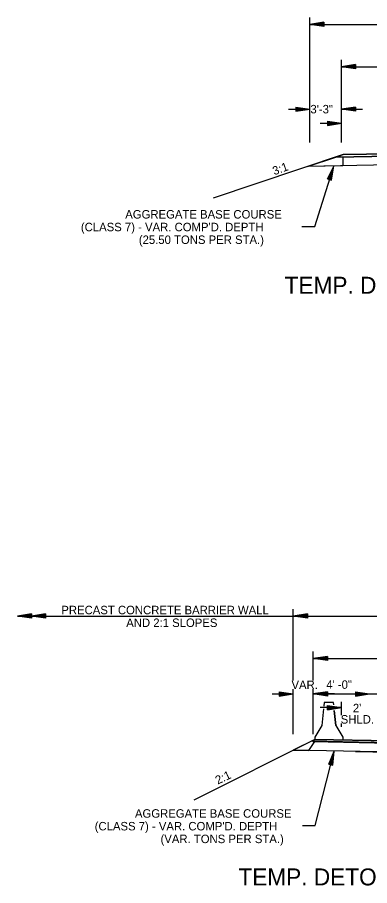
# Model space of a CAD drawing. Extents: x 138 to 3619, y -519 to 1449.
# Drawn here: x 2153 to 2402, y 302 to 917 of the extents above; entities that cross this region are included whole.
import ezdxf

# ---------------------------------------------------------------- set-up
doc = ezdxf.new("R2010")
doc.units = 0
for name, color, linetype in [('R_Annotation', 7, 'Continuous'), ('R_Barrier Wall', 7, 'Continuous'), ('R_Dimension', 7, 'Continuous'), ('R_No Plot', 7, 'Continuous')]:
    doc.layers.add(name, color=color, linetype=linetype)

msp = doc.modelspace()

# ---------------------------------------------------------------- linework, layer by layer
at = {"layer": 'R_Annotation'}
for p, q in [((2383.54, 820.01), (2291.37, 789.28)), ((2502.36, 820.55), (2378.33, 818.27)), ((2502.36, 822.22), (2383.54, 820.01)), ((2502.36, 814.3), (2358.31, 811.6)), ((2363.43, 405.81), (2277.65, 362.92)), ((2363.43, 405.81), (2362.09, 404.48)), ((2363.43, 405.81), (2642.36, 400.61)), ((2502.36, 401.55), (2360.91, 404.56)), ((2392.36, 397.37), (2658.85, 392.36))]:
    msp.add_line(p, q, dxfattribs=at)
msp.add_lwpolyline([(2502.36, 395.3), (2348.2, 398.2)], dxfattribs=at)
at = {"layer": 'R_Barrier Wall'}
for points in [[(2376.91, 430.4), (2376.74, 432.04), (2370.09, 432.04), (2369.81, 429.39)], [(2369.66, 427.51), (2368.43, 415.81), (2363.51, 407.48), (2363.43, 405.81)], [(2377.29, 426.41), (2378.41, 415.81), (2383.33, 407.48), (2383.41, 405.81)], [(2378.43, 415.81), (2377.3, 426.39)]]:
    msp.add_lwpolyline(points, dxfattribs=at)
at = {"layer": 'R_Dimension'}
for p, q in [((2359.92, 828.57), (2359.92, 917.22)), ((2369.92, 913.72), (2359.92, 912.22)), ((2359.92, 912.22), (2646.4, 912.22)), ((2369.92, 910.72), (2359.92, 912.22)), ((2369.92, 913.47), (2361.59, 912.22)), ((2369.92, 910.97), (2361.59, 912.22)), ((2369.92, 913.21), (2363.31, 912.22)), ((2369.92, 911.22), (2363.31, 912.22)), ((2369.92, 912.96), (2364.98, 912.22)), ((2369.92, 911.47), (2364.98, 912.22)), ((2369.92, 912.7), (2366.67, 912.22)), ((2369.92, 911.73), (2366.67, 912.22)), ((2369.92, 912.45), (2368.34, 912.22)), ((2369.92, 911.98), (2368.34, 912.22)), ((2369.92, 913.72), (2369.92, 910.72)), ((2382.37, 828.57), (2382.37, 887.22)), ((2392.37, 883.73), (2382.37, 882.23)), ((2382.37, 882.23), (2622.36, 882.23)), ((2392.37, 880.73), (2382.37, 882.23)), ((2392.37, 883.48), (2384.04, 882.23)), ((2392.37, 880.98), (2384.04, 882.23)), ((2392.37, 883.22), (2385.76, 882.23)), ((2392.37, 881.23), (2385.76, 882.23)), ((2392.37, 882.97), (2387.42, 882.23)), ((2392.37, 881.48), (2387.42, 882.23)), ((2392.37, 882.71), (2389.12, 882.23)), ((2392.37, 881.74), (2389.12, 882.23)), ((2392.37, 882.46), (2390.79, 882.23)), ((2392.37, 881.99), (2390.79, 882.23)), ((2392.37, 883.73), (2392.37, 880.73)), ((2344.92, 852.22), (2359.92, 852.22)), ((2349.92, 853.72), (2359.92, 852.22)), ((2349.92, 853.72), (2349.92, 850.72)), ((2349.92, 853.47), (2358.25, 852.22)), ((2349.92, 853.21), (2356.53, 852.22)), ((2349.92, 852.96), (2354.87, 852.22)), ((2349.92, 852.7), (2353.17, 852.22)), ((2349.92, 852.45), (2351.5, 852.22)), ((2349.92, 850.72), (2359.92, 852.22)), ((2349.92, 851.73), (2353.17, 852.22)), ((2349.92, 851.22), (2356.53, 852.22)), ((2349.92, 850.97), (2358.25, 852.22)), ((2349.92, 851.47), (2354.87, 852.22)), ((2349.92, 851.98), (2351.5, 852.22)), ((2392.37, 853.72), (2382.37, 852.22)), ((2392.37, 850.72), (2382.37, 852.22)), ((2382.37, 852.22), (2397.37, 852.22)), ((2392.37, 853.47), (2384.04, 852.22)), ((2392.37, 850.97), (2384.04, 852.22)), ((2392.37, 853.21), (2385.76, 852.22)), ((2392.37, 851.22), (2385.76, 852.22)), ((2392.37, 852.96), (2387.42, 852.22)), ((2392.37, 851.47), (2387.42, 852.22)), ((2392.37, 852.7), (2389.12, 852.22)), ((2392.37, 851.73), (2389.12, 852.22)), ((2392.37, 852.45), (2390.79, 852.22)), ((2392.37, 851.98), (2390.79, 852.22)), ((2392.37, 853.72), (2392.37, 850.72)), ((2372.37, 843.72), (2382.37, 842.22)), ((2372.37, 843.72), (2372.37, 840.72)), ((2372.37, 843.47), (2380.7, 842.22)), ((2372.37, 843.21), (2378.98, 842.22)), ((2372.37, 842.96), (2377.31, 842.22)), ((2372.37, 842.7), (2375.62, 842.22)), ((2372.37, 842.45), (2373.95, 842.22)), ((2367.37, 842.22), (2382.37, 842.22)), ((2372.37, 840.72), (2382.37, 842.22)), ((2372.37, 841.73), (2375.62, 842.22)), ((2372.37, 841.22), (2378.98, 842.22)), ((2372.37, 840.97), (2380.7, 842.22)), ((2372.37, 841.47), (2377.31, 842.22)), ((2372.37, 841.98), (2373.95, 842.22)), ((2358.36, 811.61), (2378.33, 818.27)), ((2502.36, 820.55), (2378.33, 818.27)), ((2378.33, 818.27), (2502.36, 820.55)), ((2378.33, 818.27), (2383.54, 820.01)), ((2383.54, 820.01), (2378.33, 818.27)), ((2378.33, 818.27), (2383.38, 818.38)), ((2383.38, 818.38), (2383.44, 812.07)), ((2383.54, 820.01), (2502.36, 822.22)), ((2502.36, 822.22), (2383.54, 820.01)), ((2383.44, 812.07), (2358.36, 811.61)), ((2372.42, 802.86), (2376.87, 811.94)), ((2375.28, 801.96), (2376.87, 811.94)), ((2372.66, 802.79), (2376.37, 810.35)), ((2372.9, 802.71), (2375.85, 808.71)), ((2373.14, 802.64), (2375.34, 807.13)), ((2373.39, 802.56), (2374.83, 805.51)), ((2374.32, 802.26), (2374.83, 805.51)), ((2374.56, 802.19), (2375.34, 807.13)), ((2374.8, 802.11), (2375.85, 808.71)), ((2375.04, 802.03), (2376.37, 810.35)), ((2372.42, 802.86), (2375.28, 801.96)), ((2373.63, 802.48), (2374.33, 803.92)), ((2374.07, 802.34), (2374.33, 803.92)), ((2348.2, 447.56), (2348.2, 498.22)), ((2162.55, 494.72), (2152.55, 493.22)), ((2152.55, 493.22), (2348.2, 493.22)), ((2162.55, 491.72), (2152.55, 493.22)), ((2162.55, 494.47), (2154.22, 493.22)), ((2162.55, 491.97), (2154.22, 493.22)), ((2162.55, 494.21), (2155.94, 493.22)), ((2162.55, 492.22), (2155.94, 493.22)), ((2162.55, 493.96), (2157.6, 493.22)), ((2162.55, 492.47), (2157.6, 493.22)), ((2162.55, 493.7), (2159.3, 493.22)), ((2162.55, 492.73), (2159.3, 493.22)), ((2162.55, 493.45), (2160.97, 493.22)), ((2162.55, 492.98), (2160.97, 493.22)), ((2162.55, 494.72), (2162.55, 491.72)), ((2172.55, 494.72), (2162.55, 493.22)), ((2172.55, 491.72), (2162.55, 493.22)), ((2172.55, 494.47), (2164.22, 493.22)), ((2172.55, 491.97), (2164.22, 493.22)), ((2172.55, 494.21), (2165.94, 493.22)), ((2172.55, 492.22), (2165.94, 493.22)), ((2172.55, 493.96), (2167.61, 493.22)), ((2172.55, 492.47), (2167.61, 493.22)), ((2172.55, 493.7), (2169.3, 493.22)), ((2172.55, 492.73), (2169.3, 493.22)), ((2172.55, 493.45), (2170.97, 493.22)), ((2172.55, 492.98), (2170.97, 493.22)), ((2172.55, 494.72), (2172.55, 491.72)), ((2358.2, 494.72), (2348.2, 493.22)), ((2348.2, 493.22), (2666.4, 493.22)), ((2358.2, 491.72), (2348.2, 493.22)), ((2358.2, 494.47), (2349.87, 493.22)), ((2358.2, 491.97), (2349.87, 493.22)), ((2358.2, 494.21), (2351.59, 493.22)), ((2358.2, 492.22), (2351.59, 493.22)), ((2358.2, 493.96), (2353.25, 493.22)), ((2358.2, 492.47), (2353.25, 493.22)), ((2358.2, 493.7), (2354.95, 493.22)), ((2358.2, 492.73), (2354.95, 493.22)), ((2358.2, 493.45), (2356.62, 493.22)), ((2358.2, 492.98), (2356.62, 493.22)), ((2358.2, 494.72), (2358.2, 491.72)), ((2362.37, 447.56), (2362.37, 468.22)), ((2372.37, 464.73), (2362.37, 463.23)), ((2362.37, 463.23), (2642.36, 463.23)), ((2372.37, 461.73), (2362.37, 463.23)), ((2372.37, 464.48), (2364.04, 463.23)), ((2372.37, 461.98), (2364.04, 463.23)), ((2372.37, 464.22), (2365.76, 463.23)), ((2372.37, 462.23), (2365.76, 463.23)), ((2372.37, 463.97), (2367.42, 463.23)), ((2372.37, 462.48), (2367.42, 463.23)), ((2372.37, 463.71), (2369.12, 463.23)), ((2372.37, 462.74), (2369.12, 463.23)), ((2372.37, 463.46), (2370.79, 463.23)), ((2372.37, 462.99), (2370.79, 463.23)), ((2372.37, 464.73), (2372.37, 461.73)), ((2333.2, 438.14), (2348.2, 438.14)), ((2338.2, 439.64), (2348.2, 438.14)), ((2338.2, 439.64), (2338.2, 436.64)), ((2338.2, 439.39), (2346.53, 438.14)), ((2338.2, 439.13), (2344.81, 438.14)), ((2338.2, 438.88), (2343.14, 438.14)), ((2338.2, 438.62), (2341.45, 438.14)), ((2338.2, 438.37), (2339.78, 438.14)), ((2338.2, 436.64), (2348.2, 438.14)), ((2338.2, 437.65), (2341.45, 438.14)), ((2338.2, 437.14), (2344.81, 438.14)), ((2338.2, 436.89), (2346.53, 438.14)), ((2338.2, 437.39), (2343.14, 438.14)), ((2338.2, 437.9), (2339.78, 438.14)), ((2348.2, 409.57), (2348.2, 441.56)), ((2362.37, 409.57), (2362.37, 441.56)), ((2372.37, 439.64), (2362.37, 438.14)), ((2362.37, 438.14), (2602.36, 438.14)), ((2372.37, 436.64), (2362.37, 438.14)), ((2377.37, 438.14), (2362.37, 438.14)), ((2372.37, 439.39), (2364.04, 438.14)), ((2372.37, 436.89), (2364.04, 438.14)), ((2372.37, 439.13), (2365.76, 438.14)), ((2372.37, 437.14), (2365.76, 438.14)), ((2372.37, 438.88), (2367.42, 438.14)), ((2372.37, 437.39), (2367.42, 438.14)), ((2372.37, 438.62), (2369.12, 438.14)), ((2372.37, 437.65), (2369.12, 438.14)), ((2372.37, 438.37), (2370.79, 438.14)), ((2372.37, 437.9), (2370.79, 438.14)), ((2372.37, 439.64), (2372.37, 436.64)), ((2392.37, 439.64), (2402.37, 438.14)), ((2392.37, 439.64), (2392.37, 436.64)), ((2392.37, 439.39), (2400.7, 438.14)), ((2392.37, 439.13), (2398.98, 438.14)), ((2392.37, 438.88), (2397.31, 438.14)), ((2392.37, 438.62), (2395.62, 438.14)), ((2392.37, 438.37), (2393.95, 438.14)), ((2392.37, 436.64), (2402.37, 438.14)), ((2392.37, 437.65), (2395.62, 438.14)), ((2392.37, 437.14), (2398.98, 438.14)), ((2392.37, 436.89), (2400.7, 438.14)), ((2392.37, 437.39), (2397.31, 438.14)), ((2392.37, 437.9), (2393.95, 438.14)), ((2382.37, 423.11), (2382.37, 432.62)), ((2382.37, 428.4), (2367.37, 428.4)), ((2372.37, 429.9), (2382.37, 428.4)), ((2372.37, 426.9), (2372.37, 429.9)), ((2372.37, 429.65), (2380.7, 428.4)), ((2372.37, 429.39), (2378.98, 428.4)), ((2372.37, 429.14), (2377.31, 428.4)), ((2372.37, 428.89), (2375.62, 428.4)), ((2372.37, 428.63), (2373.95, 428.4)), ((2372.37, 426.9), (2382.37, 428.4)), ((2372.37, 427.91), (2375.62, 428.4)), ((2372.37, 427.4), (2378.98, 428.4)), ((2372.37, 427.15), (2380.7, 428.4)), ((2372.37, 427.65), (2377.31, 428.4)), ((2372.37, 428.16), (2373.95, 428.4)), ((2382.37, 414.75), (2382.37, 417.11)), ((2363.43, 405.81), (2348.2, 398.2)), ((2363.43, 405.81), (2362.09, 404.48)), ((2362.09, 404.48), (2363.43, 405.81)), ((2502.36, 403.22), (2363.43, 405.81)), ((2362.09, 404.48), (2502.36, 401.55)), ((2348.2, 398.2), (2359.17, 397.99)), ((2373.36, 388.34), (2377.3, 397.65)), ((2373.6, 388.28), (2376.88, 396.03)), ((2373.85, 388.21), (2376.45, 394.37)), ((2375.77, 387.72), (2376.45, 394.37)), ((2376.02, 387.65), (2376.88, 396.03)), ((2376.26, 387.59), (2377.3, 397.65)), ((2373.36, 388.34), (2376.26, 387.59)), ((2374.09, 388.15), (2376.04, 392.76)), ((2374.34, 388.09), (2375.62, 391.11)), ((2374.58, 388.02), (2375.2, 389.5)), ((2375.04, 387.91), (2375.2, 389.5)), ((2375.28, 387.84), (2375.62, 391.11)), ((2375.53, 387.78), (2376.04, 392.76))]:
    msp.add_line(p, q, dxfattribs=at)
for points in [[(2354.39, 769.21), (2363.38, 769.21), (2376.87, 811.94)], [(2359.17, 397.99), (2363.38, 404.45), (2362.09, 404.48)], [(2354.82, 344.91), (2363.81, 344.91), (2377.3, 397.65)]]:
    msp.add_lwpolyline(points, dxfattribs=at)
at = {"layer": 'R_No Plot'}
for p, q in [((2383.54, 820.01), (2378.33, 818.27)), ((2378.33, 818.27), (2383.38, 818.38)), ((2383.38, 818.36), (2483.65, 820.21)), ((2383.38, 818.38), (2383.38, 818.36)), ((2502.36, 822.22), (2383.54, 820.01))]:
    msp.add_line(p, q, dxfattribs=at)

# ---------------------------------------------------------------- texts
at = {"layer": 'R_Annotation'}
for s, height, p in [('3\'-3"', 6, (2360.36, 849.22)), ('AGGREGATE BASE COURSE', 6, (2229.06, 774.75)), ("(CLASS 7) - VAR. COMP'D. DEPTH", 6, (2197.61, 765.75)), ('(25.50 TONS PER STA.)', 6, (2238.69, 756.75)), ('TEMP. DETOUR - TANGENT SECTION', 12, (2342.06, 721.52)), ('PRECAST CONCRETE BARRIER WALL', 6, (2183.74, 494.52)), ('AND 2:1 SLOPES', 6, (2229.76, 485.52)), ('VAR.', 6, (2346.93, 441.56)), ('4\' -0"', 6, (2371.61, 441.74)), ("2'", 6, (2390.49, 425.1)), ('SHLD.', 6, (2381.84, 417.11)), ('AGGREGATE BASE COURSE', 6, (2235.94, 350.46)), ("(CLASS 7) - VAR. COMP'D. DEPTH", 6, (2207.4, 341.46)), ('(VAR. TONS PER STA.)', 6, (2254.08, 332.46)), ('TEMP. DETOUR - SUPERELEVATED SECTION', 12, (2309.28, 302.53))]:
    msp.add_text(s, height=height, dxfattribs=at).set_placement(p)
for s, rotation, p in [('3:1', 19.62862, (2334.72, 805.38)), ('2:1', 24.96259, (2294.6, 373.89))]:
    msp.add_text(s, height=6, rotation=rotation, dxfattribs=at).set_placement(p)

doc.saveas('drawing.dxf')
